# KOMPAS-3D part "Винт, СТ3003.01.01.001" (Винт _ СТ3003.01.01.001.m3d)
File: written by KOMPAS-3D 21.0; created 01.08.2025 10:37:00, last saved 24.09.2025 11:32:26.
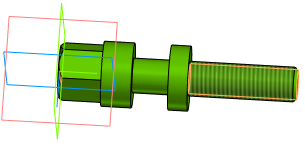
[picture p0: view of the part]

Document properties: Полное имя файла: C:\Users\1\Yandex.Disk\Документы\Новая папка\Стапель №2\Стапель _ СТ3003.00.00.000\Опора _ СТ3003.01.00.000\3D\Кронштейн _ СТ3003.01.01.000\Винт _ СТ3003.01.01.001.m3d; Автор: 1

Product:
- Part/product: Винт  | designation СТ3003.01.01.001
    Материал: Круг$d30 ГОСТ 2590-2006;Ст3сп ГОСТ 535-2005$ (density 7850 kg/m3)
    Масса: 0.311599
    Форматы листов документа: A4
    additional columns: 110

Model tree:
1. Эскиз:1
2. Элемент выдавливания:1
3. Эскиз:2
4. Элемент вращения:1
     Угол 1 = 360
5. Условное изображение резьбы:1  (with: Элемент вращения:1)  (labels: M16; cil0_24705-2004 coarse)
     Длина резьбы = 50; Шаг резьбы = 2; Номинальный диаметр резьбы = 16
6. Подгонка:1  (with: Элемент вращения:1)
7. Фаска:1  (with: Элемент вращения:1)
     Угол = 45; Длина 1 = 1.6; Длина 2 = 1.6
8. Эскиз:3  (with: Элемент выдавливания:1)
9. Элемент выдавливания:2
     Толщина стенки 1 = 8; Расстояние 2 = 20
10. Эскиз:4  (with: Элемент выдавливания:2, Фаска:1)
11. Элемент вращения:2  (labels: Круг$d30 ГОСТ 2590-2006;Ст3сп ГОСТ 535-2005$)
     Угол 1 = 360

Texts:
  СТ3003.01.01.001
